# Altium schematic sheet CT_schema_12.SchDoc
size 147 x 119 mm
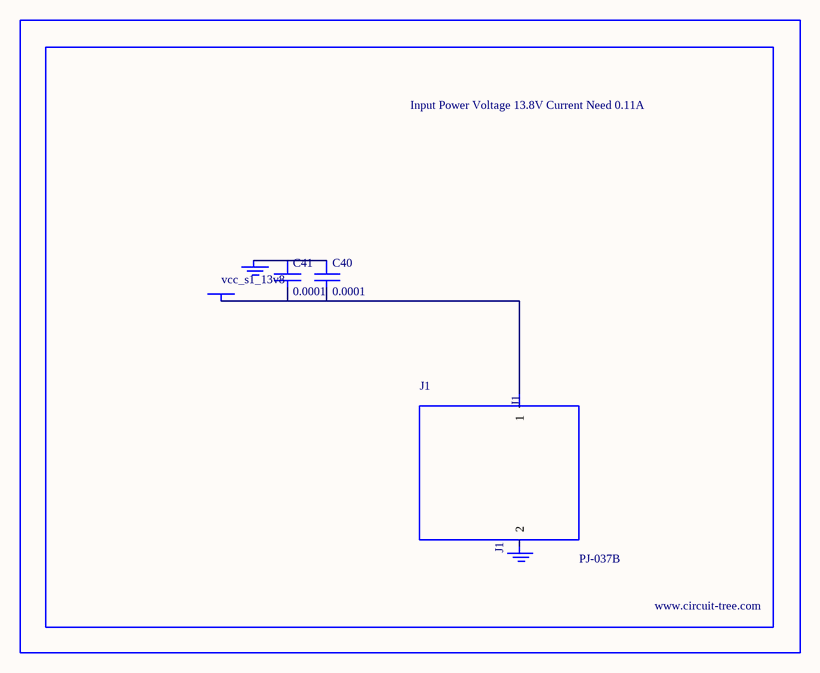
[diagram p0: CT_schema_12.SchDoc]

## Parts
BORDER11  (no value)
C40  0.0001  [EXV-9H]
C41  0.0001  [EXV-9H]
GND_INSTANCE_11_0  (no value)
GND_INSTANCE_11_1  (no value)
J1  PJ-037B  [PJ-037B_PACKAGE]
POWER_INSTANCE_11_0  vcc_s1_13v8

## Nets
NetC40_1: C40.1 C41.1 GND_INSTANCE_11_0.0(GND)
NetC40_2: C40.2 C41.2 J1.1 POWER_INSTANCE_11_0.0(PWR)

Not connected (* = marked no-connect by the designer): GND_INSTANCE_11_1 0(GND); J1 2

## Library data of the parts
BORDER11 = BORDER_PAGE11
C40 C41 = EDK107M035A9HAA
GND_INSTANCE_11_0 GND_INSTANCE_11_1 = GND
POWER_INSTANCE_11_0 = PWR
